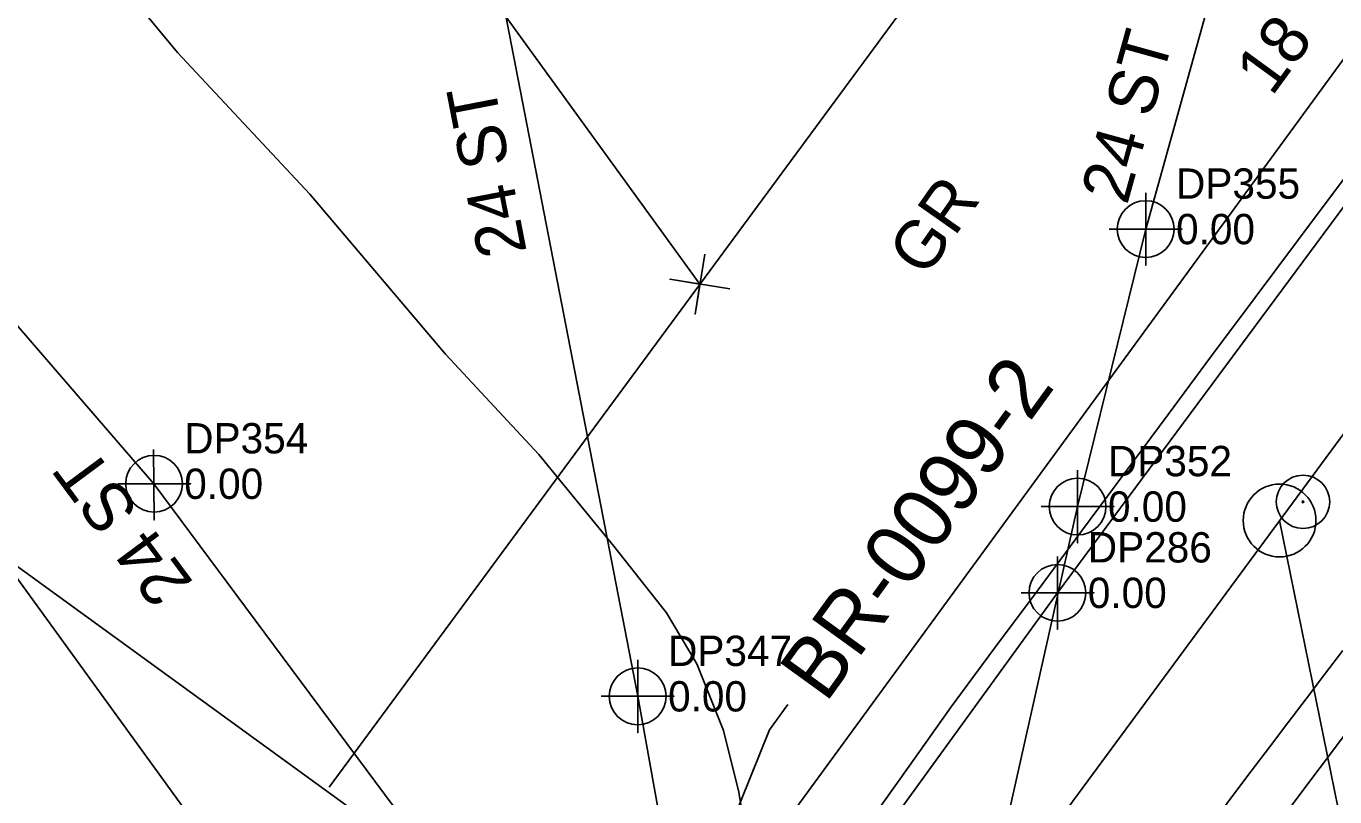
# Model space of a CAD drawing. Extents: x 1182322 to 1186765, y 572295 to 575411.
# Drawn here: x 1183757.2 to 1183865, y 573111.5 to 573175 of the extents above; entities that cross this region are included whole.
import ezdxf

# ---------------------------------------------------------------- set-up
doc = ezdxf.new("R2010")
doc.units = 0
for name, color, linetype in [('COGO Default Chain', 7, 'Continuous'), ('CTL Primary Horizontal and Vertical Leader', 7, 'Continuous'), ('CTL Primary Horizontal and Vertical Text', 7, 'Continuous'), ('Exist Horizontal Alignment', 7, 'Continuous'), ('Exist Horizontal Alignment Point', 7, 'Continuous'), ('Exist Property Corner CELL', 7, 'Continuous'), ('Exist Property Iron Pin CELL', 7, 'Continuous'), ('Exist Property Line', 7, 'Continuous'), ('Exist Right of Way Line', 7, 'Continuous'), ('Exist Roads EOP', 7, 'Continuous'), ('Exist Roads EOT', 7, 'Continuous'), ('Exist Roads Soil', 7, 'Continuous'), ('Exist Roads Soil Text', 7, 'Continuous'), ('Exist Structure Minor Pipes CMP 18 Inch', 7, 'Continuous'), ('Exist Structure Minor Pipes CMP 18 Inch Text', 7, 'Continuous'), ('Exist Utilities Telephone UG Cable SUE LOS C', 7, 'Continuous'), ('Exist Utilities Telephone UG Cable SUE LOS C Cogo Elevation', 7, 'Continuous'), ('Exist Utilities Telephone UG Cable SUE LOS C Cogo Number', 7, 'Continuous'), ('Exist Utilities Telephone UG Cable SUE LOS C Cogo Point CELL', 7, 'Continuous'), ('Exist Utilities Telephone UG Conduit SUE LOS B', 7, 'Continuous'), ('Exist Utilities Telephone UG Conduit SUE LOS B Cogo Elevation', 7, 'Continuous'), ('Exist Utilities Telephone UG Conduit SUE LOS B Cogo Number', 7, 'Continuous'), ('Exist Utilities Telephone UG Conduit SUE LOS B Cogo Point CELL', 7, 'Continuous'), ('Exist Utilities Telephone UG Conduit SUE LOS B Text', 7, 'Continuous'), ('Exist Utilities Telephone UG FO SUE LOS C', 7, 'Continuous'), ('Exist Utilities Telephone UG FO SUE LOS C Cogo Elevation', 7, 'Continuous'), ('Exist Utilities Telephone UG FO SUE LOS C Cogo Number', 7, 'Continuous'), ('Exist Utilities Telephone UG FO SUE LOS C Cogo Point CELL', 7, 'Continuous'), ('Exist Utilities Telephone UG FO SUE LOS C Text', 7, 'Continuous'), ('Exist Utilities Water UG Line SUE LOS C', 7, 'Continuous'), ('Sheet Layout Plan Border', 7, 'Continuous')]:
    doc.layers.add(name, color=color, linetype=linetype)

msp = doc.modelspace()

# ---------------------------------------------------------------- linework, layer by layer
at = {"layer": 'COGO Default Chain'}
for p, q in [((1183822.39, 573082.62), (1183960.79, 573270.41)), ((1183860.45, 573134.26), (1183879.34, 573041.3))]:
    msp.add_line(p, q, dxfattribs=at)
at = {"layer": 'CTL Primary Horizontal and Vertical Leader'}
msp.add_lwpolyline([(1183806.53, 573087.47), (1183818.43, 573117), (1183819.95, 573119.09)], dxfattribs=at)
at = {"layer": 'Exist Horizontal Alignment'}
for p, q in [((1183822.39, 573082.62), (1183960.79, 573270.41)), ((1183860.45, 573134.26), (1183879.34, 573041.3))]:
    msp.add_line(p, q, dxfattribs=at)
at = {"layer": 'Exist Horizontal Alignment Point'}
msp.add_circle((1183860.45, 573134.26), 3, dxfattribs=at)
at = {"layer": 'Exist Property Corner CELL'}
msp.add_line((1183812.7, 573153.75), (1183812.7, 573153.75), dxfattribs=at)
msp.add_lwpolyline([(1183815.17, 573153.35), (1183810.23, 573154.14), (1183812.7, 573153.75), (1183812.3, 573151.28), (1183813.09, 573156.22)], dxfattribs=at)
at = {"layer": 'Exist Property Iron Pin CELL'}
for radius in [2.2, 0.0707]:
    msp.add_circle((1183862.38, 573135.8), radius, dxfattribs=at)
at = {"layer": 'Exist Property Line'}
for p, q in [((1183812.7, 573153.75), (1183695.89, 573314.95)), ((1183668.78, 573250.38), (1183806.46, 573060.51))]:
    msp.add_line(p, q, dxfattribs=at)
at = {"layer": 'Exist Right of Way Line'}
msp.add_line((1183782.14, 573112.29), (1183920.54, 573300.08), dxfattribs=at)
at = {"layer": 'Exist Roads EOP'}
msp.add_lwpolyline([(1183813.72, 573088.92), (1183816.29, 573094.33), (1183819.43, 573099.42), (1183822.92, 573104.27), (1183826.47, 573109.14), (1183829.94, 573114.01), (1183833.39, 573118.89), (1183836.96, 573123.75), (1183840.55, 573128.55), (1183844.13, 573133.37), (1183847.7, 573138.19), (1183851.26, 573143.01), (1183854.84, 573147.82), (1183858.43, 573152.63), (1183862.02, 573157.43), (1183865.61, 573162.23), (1183869.17, 573167.06), (1183872.69, 573171.91), (1183876.2, 573176.78)], dxfattribs=at)
at = {"layer": 'Exist Roads EOT'}
msp.add_lwpolyline([(1183865.66, 573123.55), (1183864.15, 573121.56), (1183862.64, 573119.57), (1183861.13, 573117.58), (1183859.62, 573115.59), (1183858.11, 573113.59), (1183856.61, 573111.59), (1183855.12, 573109.59)], dxfattribs=at)
at = {"layer": 'Exist Roads Soil'}
msp.add_lwpolyline([(1183817.47, 573096.91), (1183817.02, 573104.88), (1183815.9, 573111.87), (1183814.65, 573116.94), (1183812.45, 573122.44), (1183809.93, 573126.66), (1183805.61, 573132.15), (1183799.42, 573139.69), (1183791.75, 573147.97), (1183780.55, 573161.17), (1183769.66, 573172.84), (1183756.41, 573188.82)], dxfattribs=at)
at = {"layer": 'Exist Structure Minor Pipes CMP 18 Inch'}
msp.add_line((1183904.05, 573224.75), (1183807.68, 573092.9), dxfattribs=at)
at = {"layer": 'Exist Utilities Telephone UG Cable SUE LOS C'}
msp.add_lwpolyline([(1183761.25, 573038.53), (1183769.09, 573034.41), (1183772.83, 573037.9), (1183792.84, 573062.44), (1183815.5, 573091.52), (1183842.15, 573128.3), (1183871.65, 573168.11), (1183894.45, 573200.64), (1183915.52, 573231.01), (1183941.95, 573268.28), (1183966.78, 573306.07), (1183979.43, 573323.54), (1183993.99, 573342.83), (1184020.65, 573379.96), (1184047.47, 573417.15), (1184074.68, 573455.3), (1184101.33, 573490.9), (1184089.43, 573505.28)], dxfattribs=at)
at = {"layer": 'Exist Utilities Telephone UG Cable SUE LOS C Cogo Point CELL'}
msp.add_lwpolyline([(1183842.15, 573131.3), (1183842.15, 573125.3), (1183842.15, 573128.3), (1183845.15, 573128.3), (1183839.15, 573128.3)], dxfattribs=at)
msp.add_circle((1183842.15, 573128.3), 2.34, dxfattribs=at)
at = {"layer": 'Exist Utilities Telephone UG Conduit SUE LOS B'}
msp.add_lwpolyline([(1183826.74, 573041.02), (1183813.39, 573051.16), (1183803.57, 573081.86), (1183792.75, 573103.56), (1183767.71, 573137.29), (1183736.2, 573173.77)], dxfattribs=at)
at = {"layer": 'Exist Utilities Telephone UG Conduit SUE LOS B Cogo Point CELL'}
msp.add_lwpolyline([(1183767.69, 573140.1), (1183767.73, 573134.29), (1183767.71, 573137.29), (1183770.73, 573137.29), (1183764.73, 573137.29)], dxfattribs=at)
msp.add_circle((1183767.73, 573137.29), 2.34, dxfattribs=at)
at = {"layer": 'Exist Utilities Telephone UG FO SUE LOS C'}
for points in [[(1183831.2, 573051.4), (1183831.99, 573067.67), (1183835.94, 573100.34), (1183843.81, 573135.41), (1183849.42, 573158.28), (1183872.21, 573240.17), (1183881.95, 573271.33), (1183882.59, 573295.88), (1183881.95, 573329.75), (1183881.17, 573370.19), (1183880.74, 573416.08), (1183881.11, 573461.73), (1183880.38, 573505.49), (1183880.23, 573552), (1183881.56, 573597.96), (1183880.77, 573642.04), (1183880.14, 573689.54)], [(1183829.91, 573050.69), (1183824.94, 573066.76), (1183812.49, 573092.36), (1183807.57, 573119.77), (1183793.41, 573192.85)]]:
    msp.add_lwpolyline(points, dxfattribs=at)
at = {"layer": 'Exist Utilities Telephone UG FO SUE LOS C Cogo Point CELL'}
for points in [[(1183849.42, 573161.28), (1183849.42, 573155.28), (1183849.42, 573158.28), (1183852.42, 573158.28), (1183846.42, 573158.28)], [(1183843.81, 573138.41), (1183843.81, 573132.41), (1183843.81, 573135.41), (1183846.81, 573135.41), (1183840.81, 573135.41)], [(1183807.57, 573122.77), (1183807.57, 573116.77), (1183807.57, 573119.77), (1183810.57, 573119.77), (1183804.57, 573119.77)]]:
    msp.add_lwpolyline(points, dxfattribs=at)
for centre in [(1183849.42, 573158.28), (1183843.81, 573135.41), (1183807.57, 573119.77)]:
    msp.add_circle(centre, 2.34, dxfattribs=at)
at = {"layer": 'Exist Utilities Water UG Line SUE LOS C'}
msp.add_line((1183822.46, 573058.84), (1183995.12, 573288.87), dxfattribs=at)
at = {"layer": 'Sheet Layout Plan Border'}
msp.add_line((1183580.54, 573258.1), (1184066.18, 572905.74), dxfattribs=at)

# ---------------------------------------------------------------- texts
at = {"layer": 'CTL Primary Horizontal and Vertical Text'}
msp.add_text('BR-0099-2', height=5, rotation=54.103, dxfattribs=at).set_placement((1183823.06, 573119.13))
at = {"layer": 'Exist Roads Soil Text'}
msp.add_text('GR', height=4, rotation=54.8611, dxfattribs=at).set_placement((1183831.27, 573154.18))
at = {"layer": 'Exist Structure Minor Pipes CMP 18 Inch Text'}
msp.add_text('18" CMP', height=4, rotation=53.8388, dxfattribs=at).set_placement((1183859.81, 573169.14))
at = {"layer": 'Exist Utilities Telephone UG Cable SUE LOS C Cogo Elevation'}
msp.add_text('0.00', height=2.5, dxfattribs=at).set_placement((1183844.65, 573127.05))
at = {"layer": 'Exist Utilities Telephone UG Cable SUE LOS C Cogo Number'}
msp.add_text('DP286', height=2.5, dxfattribs=at).set_placement((1183844.65, 573130.8))
at = {"layer": 'Exist Utilities Telephone UG Conduit SUE LOS B Cogo Elevation'}
msp.add_text('0.00', height=2.5, dxfattribs=at).set_placement((1183770.21, 573136.04))
at = {"layer": 'Exist Utilities Telephone UG Conduit SUE LOS B Cogo Number'}
msp.add_text('DP354', height=2.5, dxfattribs=at).set_placement((1183770.21, 573139.79))
at = {"layer": 'Exist Utilities Telephone UG Conduit SUE LOS B Text'}
msp.add_text('24 ST', height=4, rotation=126.5897, dxfattribs=at).set_placement((1183771.03, 573129.13))
at = {"layer": 'Exist Utilities Telephone UG FO SUE LOS C Cogo Elevation'}
for p in [(1183851.92, 573157.03), (1183846.31, 573134.16), (1183810.07, 573118.52)]:
    msp.add_text('0.00', height=2.5, dxfattribs=at).set_placement(p)
at = {"layer": 'Exist Utilities Telephone UG FO SUE LOS C Cogo Number'}
for s, p in [('DP355', (1183851.92, 573160.78)), ('DP352', (1183846.31, 573137.91)), ('DP347', (1183810.07, 573122.27))]:
    msp.add_text(s, height=2.5, dxfattribs=at).set_placement(p)
at = {"layer": 'Exist Utilities Telephone UG FO SUE LOS C Text'}
for rotation, p in [(74.4485, (1183847.88, 573160.19)), (100.9686, (1183798.44, 573156.4))]:
    msp.add_text('24 ST', height=4, rotation=rotation, dxfattribs=at).set_placement(p)

doc.saveas('drawing.dxf')
